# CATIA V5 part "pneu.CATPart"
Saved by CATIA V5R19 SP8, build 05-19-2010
Part number: pneu
Bounding box of the stored display mesh (mm): x -749.82 to 749.82, y -165 to 165, z -750 to 750
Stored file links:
  C:\Users\ThinkMotion\Desktop\EU_thinkMotion\iao\IAO_MMS_Groupe3\gdespas\projet_Thinkmotion_GDESPAS\projet Thinkmotion GDESPAS\Assemblage gdespas\pneu.CATPart
  C:\Users\ThinkMotion\Desktop\EU_thinkMotion\iao\IAO_MMS_Groupe3\gdespas\projet_Thinkmotion_GDESPAS\projet Thinkmotion GDESPAS\Assemblage gdespas\Assemblage IAO.CATProduct
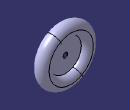
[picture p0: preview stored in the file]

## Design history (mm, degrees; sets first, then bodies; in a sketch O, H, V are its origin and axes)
External parameters (linked from other documents)
  External.diam_axe = 0.126
Body1 (main body)
  Sketch1 on yz-plane, origin (0, 0, 0), H (0, 1, 0), V (0, 0, 1)
    circle A1 centre (0, 585) radius 165
    point P1 (0, 585)
    reference intersected line E1 through (0, 0) direction (-1, 0) from xy-plane
    radius A1 = 165
    distance A1 E1 = 420
    coincidence: P1 V
  Shaft1: profile Sketch1, axis Sketch1.H, angle 360
  Sketch2 on zx-plane, origin (0, 0, 0), H (-1, 0, 0), V (0, 0, 1)
    circle A1 centre (0, 0) radius 442.8318
    circle A2 centre (0, 0) radius 63
    radius A2 = 63 {= External.diam_axe /2}
    radius A1 = 442.8318
  Pad1: profile Sketch2, direction (0, 1, 0), length 10, opposite side length 10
